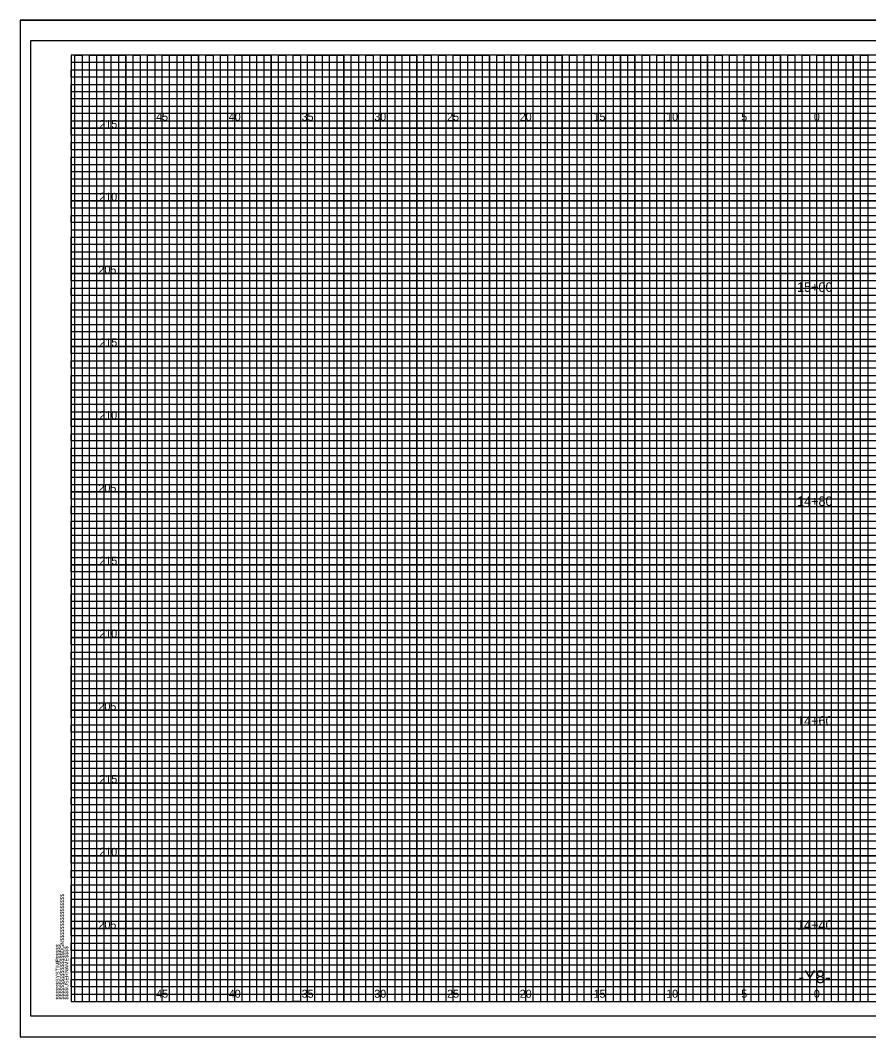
# Model space of a CAD drawing. Extents: x -4 to 103, y -2 to 209.
# Drawn here: x -3.5 to 54.8, y -2.4 to 67.4 of the extents above; entities that cross this region are included whole.
import ezdxf

# ---------------------------------------------------------------- set-up
doc = ezdxf.new("R2010")
doc.units = 0
for name, color, linetype in [('Old_Level_10', 7, 'Continuous'), ('Old_Level_16', 7, 'Continuous'), ('Old_Level_17', 7, 'Continuous'), ('Old_Level_3', 7, 'Continuous'), ('Old_Level_5', 7, 'Continuous'), ('Old_Level_6', 7, 'Continuous'), ('Old_Level_8', 7, 'Continuous'), ('Prop Dimension', 7, 'Continuous'), ('Prop Terminator CELL', 7, 'Continuous'), ('Prop XSC Text', 7, 'Continuous'), ('Typical Curb CELL', 7, 'Continuous')]:
    doc.layers.add(name, color=color, linetype=linetype)

msp = doc.modelspace()

# ---------------------------------------------------------------- linework, layer by layer
at = {"layer": 'Old_Level_10'}
for p, q in [((1.25, 0), (1.25, 65)), ((3.75, 0), (3.75, 65)), ((6.25, 0), (6.25, 65)), ((8.75, 0), (8.75, 65)), ((11.25, 0), (11.25, 65)), ((13.75, 0), (13.75, 65)), ((16.25, 0), (16.25, 65)), ((18.75, 0), (18.75, 65)), ((21.25, 0), (21.25, 65)), ((23.75, 0), (23.75, 65)), ((26.25, 0), (26.25, 65)), ((28.75, 0), (28.75, 65)), ((31.25, 0), (31.25, 65)), ((33.75, 0), (33.75, 65)), ((36.25, 0), (36.25, 65)), ((38.75, 0), (38.75, 65)), ((41.25, 0), (41.25, 65)), ((43.75, 0), (43.75, 65)), ((46.25, 0), (46.25, 65)), ((48.75, 0), (48.75, 65)), ((51.25, 0), (51.25, 65)), ((53.75, 0), (53.75, 65)), ((0, 62.5), (74.25, 62.5)), ((0, 60), (102.5, 60)), ((0, 57.5), (102.5, 57.5)), ((0, 55), (102.5, 55)), ((0, 52.5), (102.5, 52.5)), ((0, 50), (102.5, 50)), ((0, 47.5), (102.5, 47.5)), ((0, 45), (102.5, 45)), ((0, 42.5), (102.5, 42.5)), ((0, 40), (102.5, 40)), ((0, 37.5), (102.5, 37.5)), ((0, 35), (102.5, 35)), ((0, 32.5), (102.5, 32.5)), ((0, 30), (102.5, 30)), ((0, 27.5), (102.5, 27.5)), ((0, 25), (102.5, 25)), ((0, 22.5), (102.5, 22.5)), ((0, 20), (102.5, 20)), ((0, 17.5), (102.5, 17.5)), ((0, 15), (102.5, 15)), ((0, 12.5), (102.5, 12.5)), ((0, 10), (102.5, 10)), ((0, 7.5), (102.5, 7.5)), ((0, 5), (102.5, 5)), ((0, 2.5), (102.5, 2.5))]:
    msp.add_line(p, q, dxfattribs=at)
at = {"layer": 'Old_Level_17'}
for points in [[(0.25, 0), (0.25, 65), (0.75, 65), (0.75, 0), (1.75, 0), (1.75, 65), (2.25, 65), (2.25, 0), (2.75, 0), (2.75, 65), (3.25, 65), (3.25, 0), (4.25, 0), (4.25, 65), (4.75, 65), (4.75, 0), (5.25, 0), (5.25, 65), (5.75, 65), (5.75, 0), (6.75, 0), (6.75, 65), (7.25, 65), (7.25, 0), (7.75, 0), (7.75, 65), (8.25, 65), (8.25, 0), (9.25, 0), (9.25, 65), (9.75, 65), (9.75, 0), (10.25, 0), (10.25, 65), (10.75, 65), (10.75, 0), (11.75, 0), (11.75, 65), (12.25, 65), (12.25, 0), (12.75, 0), (12.75, 65), (13.25, 65), (13.25, 0), (14.25, 0), (14.25, 65), (14.75, 65), (14.75, 0), (15.75, 0), (15.25, 0), (15.25, 65), (15.75, 65), (15.75, 0), (16.75, 0), (16.75, 65), (17.25, 65), (17.25, 0), (17.75, 0), (17.75, 65), (18.25, 65), (18.25, 0), (19.25, 0), (19.25, 65), (19.75, 65), (19.75, 0), (20.25, 0), (20.25, 65), (20.75, 65), (20.75, 0), (21.75, 0), (21.75, 65), (22.25, 65), (22.25, 0), (22.75, 0), (22.75, 65), (23.25, 65), (23.25, 0), (24.25, 0), (24.25, 65), (24.75, 65), (24.75, 0), (25.25, 0), (25.25, 65), (25.75, 65), (25.75, 0), (26.75, 0), (26.75, 65), (27.25, 65), (27.25, 0), (27.75, 0), (27.75, 65), (28.25, 65), (28.25, 0), (29.25, 0), (29.25, 65), (29.75, 65), (29.75, 0), (30.25, 0), (30.25, 65), (30.75, 65), (30.75, 0)], [(30.75, 0), (31.75, 0), (31.75, 65), (32.25, 65), (32.25, 0), (32.75, 0), (32.75, 65), (33.25, 65), (33.25, 0), (34.25, 0), (34.25, 65), (34.75, 65), (34.75, 0), (35.25, 0), (35.25, 65), (35.75, 65), (35.75, 0), (36.75, 0), (36.75, 65), (37.25, 65), (37.25, 0), (37.75, 0), (37.75, 65), (37.75, 0)], [(38.25, 65), (38.25, 0), (39.25, 0), (39.25, 65), (39.75, 65), (39.75, 0), (40.25, 0), (40.25, 65), (40.75, 65), (40.75, 0), (41.75, 0), (41.75, 65), (42.25, 65), (42.25, 0), (42.75, 0), (42.75, 65), (43.25, 65), (43.25, 0), (43.75, 0), (44.25, 0), (44.25, 65), (44.75, 65), (44.75, 0), (45.25, 0), (45.25, 65), (45.75, 65), (45.75, 0), (46.75, 0), (46.75, 65), (47.25, 65), (47.25, 0), (47.75, 0), (47.75, 65), (48.25, 65), (48.25, 0), (49.25, 0), (49.25, 65), (49.75, 65), (49.75, 0), (50.25, 0), (50.25, 65), (50.75, 65), (50.75, 0), (51.75, 0), (51.75, 65), (52.25, 65), (52.25, 0), (52.75, 0), (52.75, 65), (53.25, 65), (53.25, 0), (54.25, 0), (54.25, 65), (54.75, 65), (54.75, 0), (55.25, 0)], [(0, 62), (0, 63), (74.25, 63), (74.25, 63.5), (0, 63.5), (0, 64), (74.25, 64), (74.25, 64.5), (0, 64.5)], [(102.5, 62), (0, 62)], [(102.5, 61), (0, 61), (0, 61.5), (102.5, 61.5)], [(102.5, 59.5), (0, 59.5), (0, 60.5), (102.5, 60.5)], [(102.5, 58.5), (0, 58.5), (0, 59), (102.5, 59)], [(102.5, 57), (0, 57), (0, 58), (102.5, 58)], [(102.5, 56), (0, 56), (0, 56.5), (102.5, 56.5)], [(102.5, 54.5), (0, 54.5), (0, 55.5), (102.5, 55.5)], [(102.5, 53.5), (0, 53.5), (0, 54), (102.5, 54)], [(0, 53), (102.5, 53)], [(102.5, 52), (0, 52)], [(102.5, 51), (0, 51), (0, 51.5), (102.5, 51.5)], [(102.5, 49.5), (0, 49.5), (0, 50.5), (102.5, 50.5)], [(102.5, 48.5), (0, 48.5), (0, 49), (102.5, 49)], [(102.5, 47), (0, 47), (0, 48), (102.5, 48)], [(102.5, 46), (0, 46), (0, 46.5), (102.5, 46.5)], [(102.5, 44.5), (0, 44.5), (0, 45.5), (102.5, 45.5)], [(102.5, 43.5), (0, 43.5), (0, 44), (102.5, 44)], [(102.5, 42), (0, 42), (0, 43), (102.5, 43)], [(102.5, 41), (0, 41), (0, 41.5), (102.5, 41.5)], [(102.5, 39.5), (0, 39.5), (0, 40.5), (102.5, 40.5)], [(102.5, 38.5), (0, 38.5), (0, 39), (102.5, 39)], [(102.5, 37), (0, 37), (0, 38), (102.5, 38)], [(102.5, 36), (0, 36), (0, 36.5), (102.5, 36.5)], [(102.5, 34.5), (0, 34.5), (0, 35.5), (102.5, 35.5)], [(102.5, 33.5), (0, 33.5), (0, 34), (102.5, 34)], [(102.5, 32), (0, 32), (0, 33), (102.5, 33)], [(102.5, 31), (0, 31), (0, 31.5)], [(0, 31.5), (102.5, 31.5)], [(102.5, 29.5), (0, 29.5), (0, 30.5), (102.5, 30.5)], [(102.5, 28.5), (0, 28.5), (0, 29), (102.5, 29)], [(102.5, 27), (0, 27), (0, 28), (102.5, 28)], [(102.5, 26), (0, 26), (0, 26.5), (102.5, 26.5)], [(102.5, 24.5), (0, 24.5), (0, 25.5), (102.5, 25.5)], [(102.5, 23.5), (0, 23.5), (0, 24), (102.5, 24)], [(102.5, 22), (0, 22), (0, 23), (102.5, 23)], [(102.5, 21), (0, 21), (0, 21.5), (102.5, 21.5)], [(102.5, 19.5), (0, 19.5), (0, 20.5), (102.5, 20.5)], [(102.5, 18.5), (0, 18.5), (0, 19), (102.5, 19)], [(102.5, 17), (0, 17), (0, 18), (102.5, 18)], [(102.5, 16), (0, 16), (0, 16.5), (102.5, 16.5)], [(102.5, 14.5), (0, 14.5), (0, 15.5), (102.5, 15.5)], [(102.5, 13.5), (0, 13.5), (0, 14), (102.5, 14)], [(102.5, 12), (0, 12), (0, 13), (102.5, 13)], [(102.5, 11), (0, 11), (0, 11.5), (102.5, 11.5)], [(102.5, 9.5), (0, 9.5), (0, 10.5), (102.5, 10.5)], [(102.5, 8.5), (0, 8.5), (0, 9), (102.5, 9)], [(102.5, 7), (0, 7), (0, 8), (102.5, 8)], [(102.5, 6), (0, 6), (0, 6.5), (102.5, 6.5)], [(102.5, 4.5), (0, 4.5), (0, 5.5), (102.5, 5.5)], [(102.5, 3.5), (0, 3.5), (0, 4), (102.5, 4)], [(102.5, 2), (0, 2), (0, 3), (102.5, 3)], [(102.5, 1), (0, 1), (0, 1.5), (102.5, 1.5)], [(0, 0.5), (102.5, 0.5)]]:
    msp.add_lwpolyline(points, dxfattribs=at)
at = {"layer": 'Old_Level_3'}
for p, q in [((-3.5, 67.4), (103.4, 67.4)), ((-3.5, 67.4), (-3.5, -2.425)), ((-3.5, -2.425), (103.4, -2.425))]:
    msp.add_line(p, q, dxfattribs=at)
at = {"layer": 'Old_Level_5'}
msp.add_lwpolyline([(103.4, 67.4), (-3.5, 67.4), (-3.5, -2.425), (103.4, -2.425)], close=True, dxfattribs=at)
at = {"layer": 'Old_Level_6'}
msp.add_lwpolyline([(102.5, 65), (0, 65), (0, 0), (102.5, 0)], close=True, dxfattribs=at)
at = {"layer": 'Old_Level_8'}
for points in [[(1.25, 0), (1.25, 65), (3.75, 65), (3.75, 0), (6.25, 0), (6.25, 65), (8.75, 65), (8.75, 0), (11.25, 0), (11.25, 65), (13.75, 65), (13.75, 0), (16.25, 0), (16.25, 65), (18.75, 65), (18.75, 0), (21.25, 0), (21.25, 65), (23.75, 65), (23.75, 0), (26.25, 0), (26.25, 65), (28.75, 65), (28.75, 0), (31.25, 0), (31.25, 65), (33.75, 65), (33.75, 0), (36.25, 0), (36.25, 65), (38.75, 65), (38.75, 0), (41.25, 0), (41.25, 65), (43.75, 65), (43.75, 0), (46.25, 0), (46.25, 65), (48.75, 65), (48.75, 0), (51.25, 0), (51.25, 65), (53.75, 65), (53.75, 0)], [(102.5, 60), (0, 60), (0, 62.5), (74.25, 62.5)], [(102.5, 55), (0, 55), (0, 57.5), (102.5, 57.5)], [(102.5, 50), (0, 50), (0, 52.5), (102.5, 52.5)], [(102.5, 45), (0, 45), (0, 47.5), (102.5, 47.5)], [(102.5, 40), (0, 40), (0, 42.5), (102.5, 42.5)], [(102.5, 35), (0, 35), (0, 37.5), (102.5, 37.5)], [(102.5, 30), (0, 30), (0, 32.5), (102.5, 32.5)], [(102.5, 25), (0, 25), (0, 27.5), (102.5, 27.5)], [(102.5, 20), (0, 20), (0, 22.5), (102.5, 22.5)], [(102.5, 15), (0, 15), (0, 17.5), (102.5, 17.5)], [(102.5, 10), (0, 10), (0, 12.5), (102.5, 12.5)], [(102.5, 5), (0, 5), (0, 7.5), (102.5, 7.5)], [(0, 2.5), (102.5, 2.5)]]:
    msp.add_lwpolyline(points, dxfattribs=at)
at = {"layer": 'Typical Curb CELL'}
msp.add_lwpolyline([(103, 66), (-2.8, 66), (-2.8, -1), (103, -1)], close=True, dxfattribs=at)

# ---------------------------------------------------------------- texts
at = {"layer": 'Old_Level_16'}
for s, p in [('45', (5.8399, 60.5)), ('40', (10.8313, 60.5)), ('35', (15.8399, 60.5)), ('30', (20.8313, 60.5)), ('25', (25.8399, 60.5)), ('20', (30.8313, 60.5)), ('15', (35.9058, 60.5)), ('10', (40.8971, 60.5)), ('5', (46.0574, 60.5)), ('0', (51.0488, 60.5)), ('0', (51.0488, 60.5)), ('45', (5.8399, 0.25)), ('40', (10.8313, 0.25)), ('35', (15.8399, 0.25)), ('30', (20.8313, 0.25)), ('25', (25.8399, 0.25)), ('20', (30.8313, 0.25)), ('15', (35.9058, 0.25)), ('10', (40.8971, 0.25)), ('5', (46.0574, 0.25)), ('0', (51.0488, 0.25)), ('0', (51.0488, 0.25))]:
    msp.add_text(s, height=0.55, dxfattribs=at).set_placement(p)
at = {"layer": 'Old_Level_6'}
for s, p in [('$$$$$$$$$$$$$$$$DGN$$$$$$$$$$$$$$$$', (-0.5, 0.125)), ('$$$$$$SYSTIME$$$$$', (-0.7973, 0.1247)), ('$$$$USERNAME$$$$', (-0.2, 0.125))]:
    msp.add_text(s, height=0.2625, rotation=90, dxfattribs=at).set_placement(p)
at = {"layer": 'Old_Level_8'}
msp.add_text('040397', height=0.0025, rotation=90, dxfattribs=at).set_placement((-0.0007, 64.9864))
at = {"layer": 'Prop Dimension'}
for s, p in [('215', (1.9383, 60)), ('210', (1.9296, 55)), ('205', (1.8724, 50)), ('215', (1.9383, 45)), ('210', (1.9296, 40)), ('205', (1.8724, 35)), ('215', (1.9383, 30)), ('210', (1.9296, 25)), ('205', (1.8724, 20)), ('215', (1.9383, 15)), ('210', (1.9296, 10)), ('205', (1.8724, 5))]:
    msp.add_text(s, height=0.55, dxfattribs=at).set_placement(p)
at = {"layer": 'Prop Terminator CELL'}
for s, p in [('15+00', (49.8934, 48.7461)), ('14+80', (49.8934, 34.0386)), ('14+60', (49.8934, 18.9441)), ('14+40', (49.8934, 4.9267))]:
    msp.add_text(s, height=0.65, dxfattribs=at).set_placement(p)
at = {"layer": 'Prop XSC Text'}
msp.add_text('-Y8-', height=0.875, dxfattribs=at).set_placement((49.9985, 1.25))

doc.saveas('drawing.dxf')
